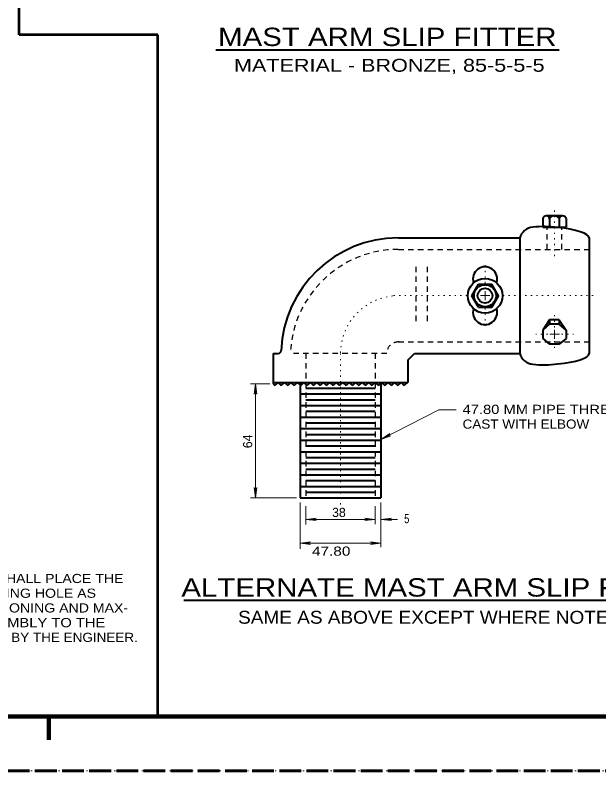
# Model space of a CAD drawing. Extents: x 312583 to 312854, y 144419 to 144597.
# Drawn here: x 312724.6 to 312772.9, y 144418.6 to 144481.2 of the extents above; entities that cross this region are included whole.
import ezdxf
from ezdxf.enums import TextEntityAlignment as Align

# ---------------------------------------------------------------- set-up
doc = ezdxf.new("R2010")
doc.units = 0
doc.header["$LTSCALE"] = 0.3
for name, pattern in [('DOTTED', [1.5, 0.3, -1.2]), ('LONG_DASHED', [7.5, 6, -1.5]), ('SHORT_DASHED', [2.7, 1.5, -1.2])]:
    doc.linetypes.add(name, pattern=pattern)
for name, color, linetype, lineweight in [('1', 7, 'Continuous', 40), ('2', 7, 'Continuous', 13), ('62', 7, 'DOTTED', 13), ('63', 7, 'LONG_DASHED', 60)]:
    doc.layers.add(name, color=color, linetype=linetype, lineweight=lineweight)

msp = doc.modelspace()

# ---------------------------------------------------------------- linework, layer by layer
at = {"layer": '1', "lineweight": 53}
for p, q in [((312736.3741, 144479.6096), (312724.8828, 144479.6096)), ((312736.3741, 144423.0846), (312736.3741, 144479.6096))]:
    msp.add_line(p, q, dxfattribs=at)
at = {"layer": '1', "linetype": 'DOTTED', "lineweight": 13}
msp.add_line((312769.2483, 144461.2556), (312769.2483, 144465.3726), dxfattribs=at)
at = {"layer": '1'}
for p, q in [((312768.29, 144464.3682), (312768.29, 144463.6552)), ((312769.9153, 144464.5982), (312768.5583, 144464.5982)), ((312768.8496, 144464.3682), (312768.8496, 144463.6552)), ((312769.647, 144464.3682), (312769.647, 144463.6552)), ((312770.2066, 144464.3682), (312770.2066, 144463.6552)), ((312768.29, 144463.6552), (312770.2066, 144463.6552)), ((312762.3943, 144457.9742), (312762.954, 144458.9402)), ((312762.9463, 144457.0236), (312762.3943, 144457.9742)), ((312768.8496, 144455.9732), (312768.29, 144455.1299)), ((312769.647, 144455.9732), (312768.8496, 144455.9732)), ((312768.8496, 144455.9732), (312768.8496, 144455.6129)), ((312769.647, 144455.9732), (312769.647, 144455.6129)), ((312768.8496, 144455.6129), (312768.29, 144455.1299)), ((312769.647, 144455.6129), (312768.8496, 144455.6129)), ((312768.29, 144455.1299), (312768.29, 144454.4399)), ((312770.2066, 144455.1299), (312770.2066, 144454.4399)), ((312768.29, 144454.4399), (312768.8496, 144453.9492)), ((312770.2066, 144454.4399), (312769.647, 144453.9492)), ((312769.647, 144453.9492), (312768.8496, 144453.9492)), ((312745.9263, 144453.1902), (312746.3633, 144453.1902)), ((312757.089, 144452.6306), (312757.6486, 144453.1902)), ((312745.9263, 144450.6679), (312746.072, 144450.5222)), ((312746.3403, 144450.7906), (312746.072, 144450.5222)), ((312746.3403, 144450.7906), (312746.6086, 144450.5222)), ((312746.877, 144450.7906), (312746.6086, 144450.5222)), ((312746.877, 144450.7906), (312747.1453, 144450.5222)), ((312747.4136, 144450.7906), (312747.1453, 144450.5222)), ((312747.4136, 144450.7906), (312747.682, 144450.5222)), ((312747.9503, 144450.7906), (312747.682, 144450.5222)), ((312747.9503, 144450.7906), (312748.2186, 144450.5222)), ((312748.487, 144450.7906), (312748.2186, 144450.5222)), ((312748.487, 144450.7906), (312748.7553, 144450.5222)), ((312749.0236, 144450.7906), (312748.7553, 144450.5222)), ((312749.0236, 144450.7906), (312749.292, 144450.5222)), ((312749.5603, 144450.7906), (312749.292, 144450.5222)), ((312749.5603, 144450.7906), (312749.8286, 144450.5222)), ((312750.097, 144450.7906), (312749.8286, 144450.5222)), ((312750.097, 144450.7906), (312750.3653, 144450.5222)), ((312750.6336, 144450.7906), (312750.3653, 144450.5222)), ((312750.6336, 144450.7906), (312750.902, 144450.5222)), ((312751.1703, 144450.7906), (312750.902, 144450.5222)), ((312751.1703, 144450.7906), (312751.4386, 144450.5222)), ((312751.707, 144450.7906), (312751.4386, 144450.5222)), ((312751.707, 144450.7906), (312751.9753, 144450.5222)), ((312752.2436, 144450.7906), (312751.9753, 144450.5222)), ((312752.2436, 144450.7906), (312752.512, 144450.5222)), ((312752.7803, 144450.7906), (312752.512, 144450.5222)), ((312752.7803, 144450.7906), (312753.0486, 144450.5222)), ((312753.317, 144450.7906), (312753.0486, 144450.5222)), ((312753.317, 144450.7906), (312753.5853, 144450.5222)), ((312753.8536, 144450.7906), (312753.5853, 144450.5222)), ((312753.8536, 144450.7906), (312754.122, 144450.5222)), ((312754.3903, 144450.7906), (312754.122, 144450.5222)), ((312754.3903, 144450.7906), (312754.6586, 144450.5222)), ((312754.927, 144450.7906), (312754.6586, 144450.5222)), ((312754.927, 144450.7906), (312755.1953, 144450.5222)), ((312755.4636, 144450.7906), (312755.1953, 144450.5222)), ((312755.4636, 144450.7906), (312755.732, 144450.5222)), ((312756.0003, 144450.7906), (312755.732, 144450.5222)), ((312756.0003, 144450.7906), (312756.2686, 144450.5222)), ((312756.537, 144450.7906), (312756.2686, 144450.5222)), ((312756.537, 144450.7906), (312756.8053, 144450.5222)), ((312757.089, 144450.8136), (312756.8053, 144450.5222))]:
    msp.add_line(p, q, dxfattribs=at)
at = {"layer": '1', "linetype": 'SHORT_DASHED', "lineweight": 25}
for p, q in [((312768.635, 144461.8152), (312768.635, 144463.6552)), ((312769.8616, 144461.8152), (312769.8616, 144463.6552)), ((312755.3563, 144453.1902), (312747.3676, 144453.1902))]:
    msp.add_line(p, q, dxfattribs=at)
at = {"layer": '1', "lineweight": 158}
for p, q in [((312616.5, 144423.0846), (312849, 144423.0846)), ((312727.35, 144421.1646), (312727.35, 144423.0846))]:
    msp.add_line(p, q, dxfattribs=at)
at = {"layer": '1', "lineweight": 53}
msp.add_lwpolyline([(312724.8828, 144479.6096), (312724.8828, 144516.6626), (312724.8828, 144585.0846)], dxfattribs=at)
at = {"layer": '1'}
for points in [[(312764.0503, 144457.0236), (312764.6023, 144457.9742), (312764.0503, 144458.9402)], [(312769.647, 144455.9732), (312770.2066, 144455.1299), (312769.647, 144455.6129)]]:
    msp.add_lwpolyline(points, dxfattribs=at)
for radius in [1.4375, 0.9135, 0.6133]:
    msp.add_circle((312763.4983, 144457.9781), radius, dxfattribs=at)
for centre, radius, start, end in [((312768.5698, 144464.3133), 0.2852, 11.10854, 168.89146), ((312769.2483, 144464.1377), 0.4605, 30.03672, 149.96328), ((312769.9268, 144464.3133), 0.2852, 11.10854, 168.89146), ((312767.572, 144462.417), 1.2495, 95.48732, 163.60099), ((312768.3416, 144455.8195), 7.8896, 81.60394, 96.45767), ((312763.4983, 144459.3654), 1.0085, 341.857, 198.14299), ((312763.4983, 144456.5907), 1.0085, 161.85701, 18.143), ((312746.3599, 144453.4298), 0.2396, 270, 358.87648), ((312767.572, 144453.5392), 1.2495, 196.39901, 264.51268), ((312768.3416, 144460.1366), 7.8896, 263.54233, 278.39606)]:
    msp.add_arc(centre, radius, start, end, dxfattribs=at)
at = {"layer": '1', "linetype": 'SHORT_DASHED', "lineweight": 25}
for centre, radius, start, end in [((312756.3108, 144452.8606), 8.9516, 90, 177.914), ((312756.3108, 144453.1864), 0.9583, 85.17923, 180)]:
    msp.add_arc(centre, radius, start, end, dxfattribs=at)
at = {"layer": '1', "linetype": 'DOTTED', "lineweight": 13}
msp.add_arc((312756.3108, 144453.1864), 4.7917, 95.60113, 180, dxfattribs=at)
at = {"layer": '1'}
for centre, major_axis, start_param, end_param in [((312769.257, 144462.9692), (-2.868, 0.2006), 3.1430433, 4.6456527), ((312769.257, 144452.987), (-2.868, -0.2006), 1.6375326, 3.140142)]:
    msp.add_ellipse(centre, major_axis=major_axis, ratio=0.235384, start_param=start_param, end_param=end_param, dxfattribs=at)
at = {"layer": '2', "lineweight": 40}
for p, q in [((312741.1949, 144478.3707), (312769.6482, 144478.3707)), ((312756.3146, 144462.7736), (312766.3733, 144462.7736)), ((312766.3733, 144462.7736), (312766.3733, 144453.1902)), ((312772.1233, 144462.7736), (312772.1233, 144453.1902)), ((312762.954, 144458.9402), (312764.0503, 144458.9402)), ((312762.9463, 144457.0236), (312764.0503, 144457.0236)), ((312745.9263, 144453.1902), (312745.9263, 144450.6679)), ((312757.6486, 144453.1902), (312766.3733, 144453.1902)), ((312757.089, 144452.6306), (312757.089, 144450.7906)), ((312745.9263, 144450.7906), (312757.089, 144450.7906)), ((312748.165, 144450.7906), (312748.165, 144441.2072)), ((312748.648, 144450.3152), (312754.398, 144450.3152)), ((312754.8733, 144450.7906), (312754.8733, 144441.2072)), ((312748.165, 144449.8322), (312754.8733, 144449.8322)), ((312748.648, 144449.3569), (312754.398, 144449.3569)), ((312748.165, 144448.8739), (312754.8733, 144448.8739)), ((312748.648, 144448.3986), (312754.398, 144448.3986)), ((312748.165, 144447.9156), (312754.8733, 144447.9156)), ((312748.648, 144447.4402), (312754.398, 144447.4402)), ((312748.165, 144446.9572), (312754.8733, 144446.9572)), ((312748.648, 144446.4819), (312754.398, 144446.4819)), ((312748.165, 144445.9989), (312754.8733, 144445.9989)), ((312748.648, 144445.5236), (312754.398, 144445.5236)), ((312748.165, 144445.0406), (312754.8733, 144445.0406)), ((312748.165, 144444.0822), (312754.8733, 144444.0822)), ((312748.648, 144444.5652), (312754.398, 144444.5652)), ((312748.648, 144443.6069), (312754.398, 144443.6069)), ((312748.165, 144443.1239), (312754.8733, 144443.1239)), ((312748.165, 144442.1656), (312754.8733, 144442.1656)), ((312748.648, 144442.6486), (312754.398, 144442.6486)), ((312748.648, 144441.6902), (312754.398, 144441.6902)), ((312748.165, 144441.2072), (312754.8733, 144441.2072)), ((312738.5429, 144432.7279), (312781.4178, 144432.7279))]:
    msp.add_line(p, q, dxfattribs=at)
at = {"layer": '2', "linetype": 'SHORT_DASHED', "lineweight": 25}
for p, q in [((312756.3146, 144461.8152), (312772.1233, 144461.8152)), ((312757.7483, 144460.3739), (312757.7483, 144455.5822)), ((312758.7066, 144460.3739), (312758.7066, 144455.5822)), ((312756.3146, 144454.1486), (312772.1233, 144454.1486)), ((312748.648, 144453.1902), (312748.648, 144441.2072)), ((312748.648, 144453.1902), (312748.648, 144450.7906)), ((312754.398, 144453.1902), (312754.398, 144441.2072)), ((312754.398, 144453.1902), (312754.398, 144450.7906))]:
    msp.add_line(p, q, dxfattribs=at)
at = {"layer": '2', "linetype": 'DOTTED'}
for p, q in [((312763.4983, 144458.5569), (312763.4983, 144460.7879)), ((312762.9233, 144457.9819), (312755.847, 144457.9819)), ((312764.0733, 144457.9819), (312772.453, 144457.9819)), ((312763.4983, 144457.4069), (312763.4983, 144455.1682)), ((312769.2636, 144455.3522), (312769.2636, 144456.5482)), ((312768.6886, 144454.7772), (312767.6996, 144454.7772)), ((312769.8463, 144454.7772), (312770.8276, 144454.7772)), ((312769.2636, 144454.2022), (312769.2636, 144453.4202)), ((312751.523, 144453.1902), (312751.523, 144440.2489))]:
    msp.add_line(p, q, dxfattribs=at)
at = {"layer": '2'}
for p, q in [((312763.4983, 144457.9819), (312763.115, 144457.9819)), ((312763.4983, 144457.9819), (312763.4983, 144458.3652)), ((312763.4983, 144457.9819), (312763.8816, 144457.9819)), ((312763.4983, 144457.9819), (312763.4983, 144457.5986)), ((312769.2636, 144454.7772), (312768.8803, 144454.7772)), ((312769.2636, 144454.7772), (312769.2636, 144455.1606)), ((312769.2636, 144454.7772), (312769.6546, 144454.7772)), ((312769.2636, 144454.7772), (312769.2636, 144454.3939)), ((312745.6656, 144450.6679), (312744.0633, 144450.6679)), ((312744.4696, 144450.6679), (312744.3623, 144449.8016)), ((312744.4696, 144441.2072), (312744.4696, 144450.6679)), ((312744.4696, 144450.6679), (312744.577, 144449.8016)), ((312744.3623, 144449.8016), (312744.4696, 144450.0776)), ((312744.577, 144449.8016), (312744.4696, 144450.0776)), ((312754.8733, 144446.0449), (312755.594, 144446.5432)), ((312755.594, 144446.5432), (312755.4023, 144446.3209)), ((312754.8733, 144446.0449), (312755.6936, 144446.3516)), ((312755.6936, 144446.3516), (312755.4023, 144446.3209)), ((312744.3623, 144442.0736), (312744.4696, 144441.7976)), ((312744.4696, 144441.2072), (312744.3623, 144442.0736)), ((312744.577, 144442.0736), (312744.4696, 144441.7976)), ((312744.4696, 144441.2072), (312744.577, 144442.0736)), ((312747.8583, 144441.2072), (312744.0633, 144441.2072)), ((312748.165, 144440.8392), (312748.165, 144436.9982)), ((312754.8733, 144440.8392), (312754.8733, 144437.1209)), ((312748.648, 144440.5249), (312748.648, 144438.9992)), ((312754.398, 144440.5249), (312754.398, 144439.0452)), ((312748.648, 144439.4362), (312749.5143, 144439.5436)), ((312748.648, 144439.4362), (312754.398, 144439.4362)), ((312748.648, 144439.4362), (312749.5143, 144439.3289)), ((312749.5143, 144439.5436), (312749.2383, 144439.4362)), ((312749.5143, 144439.3289), (312749.2383, 144439.4362)), ((312753.5316, 144439.5436), (312753.8076, 144439.4362)), ((312754.398, 144439.4362), (312753.5316, 144439.5436)), ((312753.5316, 144439.3289), (312753.8076, 144439.4362)), ((312754.398, 144439.4362), (312753.5316, 144439.3289)), ((312754.8733, 144439.4362), (312755.7396, 144439.5436)), ((312754.8733, 144439.4362), (312756.2303, 144439.4362)), ((312754.8733, 144439.4362), (312755.7396, 144439.3289)), ((312755.7396, 144439.5436), (312755.4636, 144439.4362)), ((312755.7396, 144439.3289), (312755.4636, 144439.4362)), ((312748.165, 144437.4659), (312749.0313, 144437.5732)), ((312748.165, 144437.4659), (312754.8733, 144437.4659)), ((312748.165, 144437.4659), (312749.0313, 144437.3586)), ((312749.0313, 144437.5732), (312748.7553, 144437.4659)), ((312749.0313, 144437.3586), (312748.7553, 144437.4659)), ((312754.007, 144437.5732), (312754.283, 144437.4659)), ((312754.8733, 144437.4659), (312754.007, 144437.5732)), ((312754.007, 144437.3586), (312754.283, 144437.4659)), ((312754.8733, 144437.4659), (312754.007, 144437.3586))]:
    msp.add_line(p, q, dxfattribs=at)
msp.add_lwpolyline([(312754.8733, 144446.0449), (312759.665, 144448.5212), (312761.091, 144448.5212)], dxfattribs=at)
at = {"layer": '2', "lineweight": 40}
msp.add_arc((312756.3108, 144453.0522), 9.7189, 90, 177.80004, dxfattribs=at)
at = {"layer": '62'}
msp.add_lwpolyline([(312601.2, 144418.5846), (312853.5, 144418.5846), (312853.5, 144596.7846)], dxfattribs=at)
at = {"layer": '63'}
msp.add_line((312851.75, 144418.5846), (312583.526, 144418.5846), dxfattribs=at)

# ---------------------------------------------------------------- texts
at = {"layer": '2'}
for s, height, width, p in [('MAST ARM SLIP FITTER', 1.52, 1.2, (312755.3988, 144478.6756)), ('MATERIAL - BRONZE, 85-5-5-5', 1.07, 1.25, (312755.5598, 144476.5437)), ('ALTERNATE MAST ARM SLIP FITTER', 1.52, 1.2, (312759.8793, 144433.0327)), ('SAME AS ABOVE EXCEPT WHERE NOTED', 1.07, 1.1, (312758.9496, 144430.784))]:
    msp.add_text(s, height=height, dxfattribs=dict(at, width=width)).set_placement(p, align=Align.CENTER)
for s, width, p in [('47.80 MM PIPE THREAD', 1.2, (312761.6353, 144448.1752)), ('CAST WITH ELBOW', 1.1, (312761.6353, 144446.9552)), ('5', 0.75, (312756.7975, 144439.1171)), (' 47.80', 1.25, (312748.807, 144436.4232)), ('ON INSTALLATION THE CONTRACTOR SHALL PLACE THE', 1.15, (312701.0585, 144434.1546)), ('BUSHING IN THE APPROPRIATE MOUNTING HOLE AS', 1.15, (312701.0585, 144432.9346)), ('REQUIRED TO OBTAIN VERTICAL POSITIONING AND MAX-', 1.15, (312701.0585, 144431.7146)), ('IMUM VISIBILITY OF THE SIGNAL ASSEMBLY TO THE ', 1.2, (312701.0585, 144430.4946)), ('APPROACH ROADWAY AND AS DIRECTED BY THE ENGINEER.', 1.1, (312701.0585, 144429.2746))]:
    msp.add_text(s, height=0.76, dxfattribs=dict(at, width=width)).set_placement(p)
msp.add_text('64', height=0.76, rotation=90, dxfattribs=at).set_placement((312744.2027, 144445.3361))
msp.add_text('38', height=0.76, dxfattribs=at).set_placement((312750.8226, 144439.6326))

doc.saveas('drawing.dxf')
